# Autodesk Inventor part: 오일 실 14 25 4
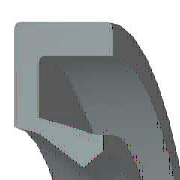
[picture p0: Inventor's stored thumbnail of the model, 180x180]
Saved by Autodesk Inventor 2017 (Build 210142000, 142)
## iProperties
Created: 2012-02
Part Number: 오일 실 14 25 4
Material: 고무
Description: 오일 실 - 스프링 장착, 비스프링, 고무 덮개 G
Document SubType Name: Modeling
Standard: JIS B 2402
Designer: mdu-01
Standards Organization: JIS
Language: ko-KR
Size Designation: 14 25 4 A
Categories: <MemberInstance><Categories><Category DisplayName="샤프트 부품" InternalName="7f7aeb1f-a693-4053-b835-cee3144e0d98" Mnemonic="SHFT"><Category DisplayName="실링" Intern
Density: 0.93 g/cm^3
Appearance: 고무 - 검은색 - 버전 1.1
IsCustomPart: 1
Author: mdu-01
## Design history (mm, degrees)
body "Solid1"
revolve "회전1" stored, may be unused: angle "d29" = 360 deg
chamfer "모따기1" distance "d30" = 0.2 (= 0.05 x b); stored, may be unused: second distance "d31" = 0.4 (= 0.1 x b), angle "d39" = 45 deg
chamfer "모따기2" distance "d32" = 0.4 (= 0.1 x b); stored, may be unused: second distance "d33" = 0.2 (= 0.05 x b), angle "d40" = 45 deg
fillet "모깎기1" dims "d34" = 0.2 (= 0.05 x b)
sketch "스케치2"
  geometry: L1 (7.914, -2.75)-(8.189, -4); L2 (7.547, -2.626)-(7.914, -2.75); L3 (7, -1.376)-(7.547, -2.626); L4 (8, -0.976)-(7, -1.376); L5 (8.956, -3)-(8, -0.976); L6 (10.056, -3)-(8.956, -3); L7 (11.278, -1)-(10.056, -3); L8 (11.278, 0)-(11.278, -1); L9 (12.5, 0)-(11.278, 0); L10 (12.5, -4)-(12.5, 0); L11 (8.189, -4)-(12.5, -4); L12 (0, -9.6)-(0, 1.6) reference; L13 (28, 0)-(14, 0) reference
  constraints: 22 end point, 3 horizontal, 2 vertical
  dimensions: "d2" = 4 distance of L10.start L9.start (= b); "d4" = 1 vertical distance of L5.start L1.end (= 0.25 x b); "d6" = 1.22222 distance of L9.start L8.start (= 0.111111 x dd - 0.111111 x Diam); "d8" = 1 distance of L8.start L7.start (= 0.25 x b); "d10" = 1.22222 horizontal distance of L7.start L6.start (= 0.111111 x dd - 0.111111 x Diam); "d12" = 0.97561 vertical distance of L9.start L4.start (= 0.243902 x b); "d14" = 1 horizontal distance of L4.start L3.start (= 0.0909091 x dd - 0.0909091 x Diam); "d16" = 0.4 vertical distance of L4.start L3.start (= 0.1 x b); "d18" = 1.1 distance of L6.start L5.start (= 0.1 x dd - 0.1 x Diam); "d20" = 1.25 vertical distance of L3.start L2.start (= 0.3125 x b); "d22" = 0.54726 horizontal distance of L3.start L2.start (= 0.0497512 x dd - 0.0497512 x Diam); "d24" = 0.275 horizontal distance of L1.start L1.end (= 0.025 x dd - 0.025 x Diam); "d26" = 1.25 vertical distance of L1.start L1.end (= 0.3125 x b); "d28" = 0.36667 horizontal distance of L2.start L1.start (= 0.0333333 x dd - 0.0333333 x Diam); "d35" = 0 distance between parallel lines of L13 L9; "d36" = 12.5 distance between parallel lines of L12 L10 (= 0.5 x dd); "d37" = 7 distance from line of L12 L3.start (= 0.5 x Diam)
other parameters: "dd" = 25 [user parameter; used in 8 equation terms], "Diam" = 14 [user parameter; used in 8 equation terms], "b" = 4 [user parameter; used in 12 equation terms], "d1" = 8 (derived), "d3" = 2 (derived), "d5" = 2.22222 (derived), "d7" = 2 (derived), "d9" = 2.22222 (derived), "d11" = 1.95122 (derived), "d13" = 1.81818 (derived), "d15" = 0.8 (derived), "d17" = 2 (derived), "d19" = 2.5 (derived), "d21" = 0.99502 (derived), "d23" = 0.5 (derived), "d25" = 2.5 (derived), "d27" = 0.66667 (derived), "d38" = 0
